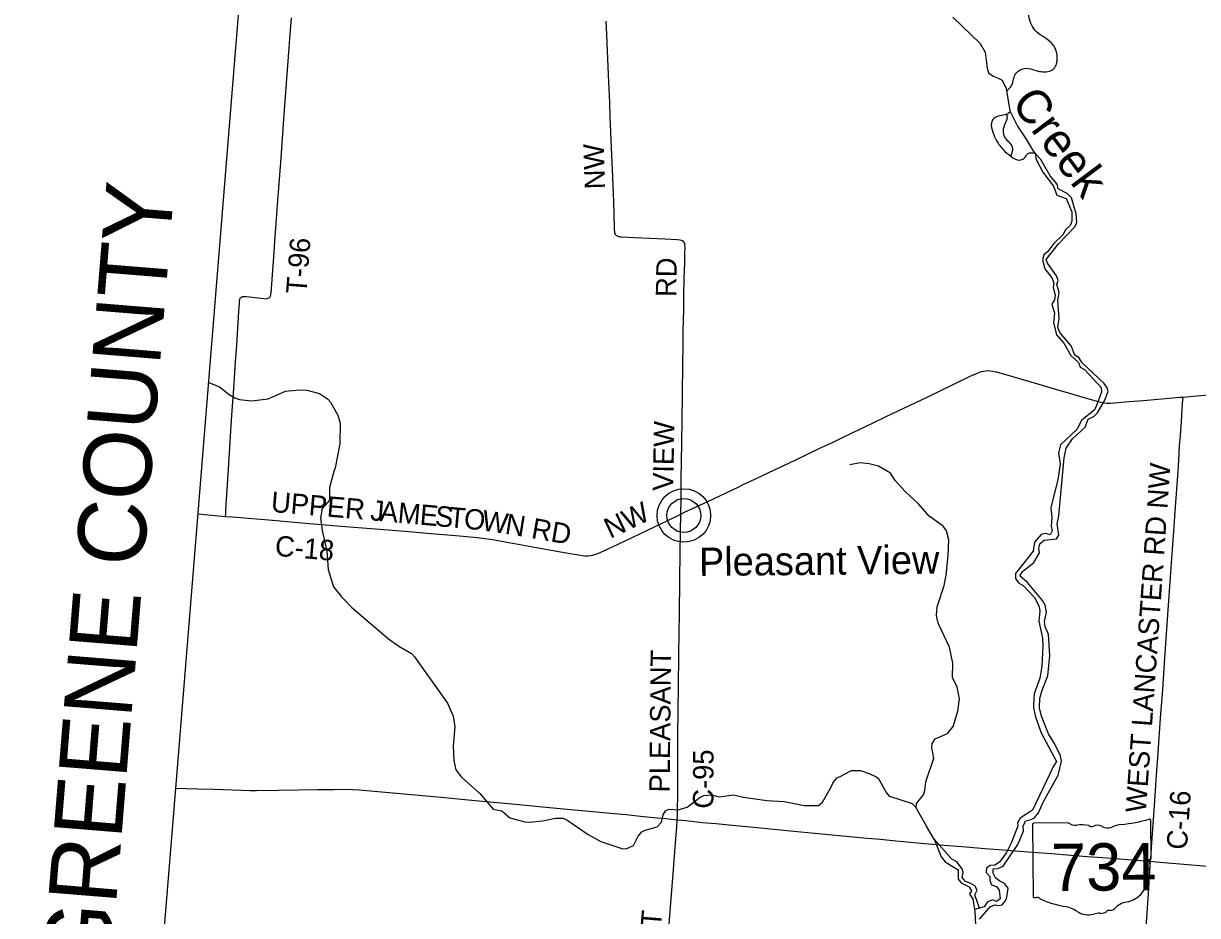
# Model space of a CAD drawing. Extents: x -51392 to 1635000, y 156707 to 696232.
# Drawn here: x 74563 to 91823, y 527835 to 540953 of the extents above; entities that cross this region are included whole.
import ezdxf

# ---------------------------------------------------------------- set-up
doc = ezdxf.new("R2010")
doc.units = 0
for name, color, linetype in [('GM_X_Adjacent_County', 7, 'Continuous'), ('GM_X_Adjacent_County_Text', 7, 'Continuous'), ('GM_X_County', 7, 'Continuous'), ('GM_X_County_Road', 7, 'Continuous'), ('GM_X_County_Road_Text', 7, 'Continuous'), ('GM_X_Major_River', 7, 'Continuous'), ('GM_X_Major_River_Text', 7, 'Continuous'), ('GM_X_Minor_River', 7, 'Continuous'), ('GM_X_State_Route', 7, 'Continuous'), ('GM_X_State_Shield', 7, 'Continuous'), ('GM_X_Township', 7, 'Continuous'), ('GM_X_Township_Road', 7, 'Continuous'), ('GM_X_Township_Road_Text', 7, 'Continuous'), ('GM_X_Unincorporated', 7, 'Continuous'), ('GM_X_Unincorporated_Text', 7, 'Continuous')]:
    doc.layers.add(name, color=color, linetype=linetype)

msp = doc.modelspace()

# ---------------------------------------------------------------- linework, layer by layer
at = {"layer": 'GM_X_Adjacent_County'}
msp.add_lwpolyline([(74563, 502065), (74862, 505867), (75172, 509582), (75227, 510268), (75674, 515788), (75743, 516628), (75955, 519254), (76337, 523966), (76597, 527182), (76801, 529705), (77124, 533695), (77266, 535451), (77972, 544170), (78206, 547064), (78655, 552615), (78677, 552881), (79341, 561012)], dxfattribs=at)
at = {"layer": 'GM_X_County'}
msp.add_lwpolyline([(74563, 502065), (74862, 505867), (75172, 509582), (75227, 510268), (75674, 515788), (75743, 516628), (75955, 519254), (76337, 523966), (76597, 527182), (76801, 529705), (77124, 533695), (77266, 535451), (77972, 544170), (78206, 547064), (78655, 552615), (80912, 552436), (84311, 552167), (86696, 551986), (89363, 551763), (96623, 551154), (109974, 550151)], dxfattribs=at)
at = {"layer": 'GM_X_County_Road'}
for points in [[(84227, 533737), (84231, 533956), (84233, 534251), (84239, 534776), (84250, 535481), (84257, 535957), (84261, 536203), (84263, 536432), (84269, 536744), (84273, 536957), (84278, 537203), (84283, 537433), (84286, 537564), (84288, 537662), (84287, 537695), (84284, 537710), (84280, 537725), (84273, 537739), (84262, 537749), (84249, 537757), (84235, 537762), (84219, 537765), (84171, 537770), (83990, 537779), (83548, 537802), (83351, 537811), (83334, 537812), (83318, 537815), (83301, 537820), (83286, 537828), (83273, 537840), (83264, 537854), (83258, 537870), (83255, 537887), (83253, 537921), (83247, 538167), (83235, 538462), (83208, 539134), (83190, 539576), (83181, 539789), (83162, 540199), (83137, 540789), (83130, 540986)], [(84227, 533737), (84282, 533764), (84624, 533924), (85069, 534136), (85143, 534171), (85314, 534252), (85521, 534351), (85907, 534532), (86292, 534715), (86455, 534793), (86604, 534863), (86841, 534976), (87033, 535068), (87254, 535176), (87506, 535297), (87847, 535459), (88231, 535643), (88482, 535765), (88587, 535812), (88618, 535825), (88650, 535835), (88682, 535842), (88715, 535847), (88748, 535848), (88781, 535846), (88814, 535841), (88863, 535830), (89021, 535786), (89540, 535633), (89682, 535592), (89871, 535536), (90170, 535450), (90360, 535396), (90423, 535380), (90455, 535374), (90487, 535371), (90536, 535370), (90601, 535373), (90814, 535392), (91026, 535410), (91239, 535428), (91353, 535438), (91566, 535456), (91612, 535459)], [(91612, 535459), (91811, 535475), (91991, 535491), (92187, 535509), (92367, 535525), (92612, 535545), (92841, 535564), (93119, 535588), (93282, 535602), (93462, 535617), (93528, 535621), (93561, 535621), (93568, 535620)], [(91131, 528632), (91134, 528674), (91151, 528903), (91184, 529378), (91203, 529672), (91220, 529901), (91243, 530228), (91280, 530735), (91311, 531160), (91342, 531618), (91368, 531978), (91388, 532256), (91407, 532534), (91427, 532812), (91455, 533221), (91473, 533483), (91493, 533777), (91517, 534104), (91536, 534366), (91547, 534530), (91560, 534742), (91570, 534890), (91585, 535102), (91603, 535364), (91607, 535413), (91612, 535459)], [(77132, 533741), (77226, 533732), (77535, 533705)], [(77535, 533705), (77635, 533697), (77929, 533672), (78224, 533647), (78763, 533601), (78943, 533586), (79172, 533566), (79417, 533545), (79859, 533510), (80170, 533485), (80497, 533457), (80971, 533417), (81232, 533392), (81347, 533380), (81428, 533367), (81783, 533304), (82106, 533247), (82543, 533170), (82720, 533138), (82785, 533129), (82818, 533125), (82850, 533124), (82866, 533124), (82898, 533128), (82930, 533134), (82961, 533143), (83007, 533160), (83097, 533200), (83305, 533297), (83838, 533551), (84045, 533651), (84227, 533737)], [(84174, 529243), (84178, 529298), (84180, 529396), (84181, 529609), (84182, 529937), (84184, 530495), (84187, 530839), (84192, 531233), (84203, 532037), (84206, 532234), (84213, 532808), (84218, 533136), (84224, 533496), (84227, 533726), (84227, 533737)], [(83940, 526285), (83951, 526420), (83985, 526845), (84013, 527205), (84031, 527434), (84053, 527712), (84094, 528202), (84114, 528447), (84149, 528905), (84168, 529134), (84174, 529243)], [(91045, 527333), (91085, 527938), (91105, 528233), (91117, 528413), (91131, 528632)]]:
    msp.add_lwpolyline(points, dxfattribs=at)
at = {"layer": 'GM_X_Major_River'}
for points in [[(88223, 541043), (88628, 540656), (88701, 540530), (88728, 540295), (88750, 540225), (88816, 540177), (88894, 540148), (88950, 540120), (89009, 539994), (89064, 539669), (89175, 539442), (89296, 539268), (89412, 539070), (89441, 539038)], [(89441, 539038), (89445, 538960), (89549, 538764), (89706, 538558), (89755, 538428), (89893, 538381), (89976, 538183), (89976, 538044), (89951, 537980), (89883, 537920), (89843, 537843), (89708, 537719), (89624, 537598), (89561, 537548), (89545, 537475), (89577, 537347), (89682, 537212), (89712, 537140), (89700, 537071), (89729, 536955), (89719, 536891), (89681, 536827), (89720, 536693), (89707, 536553), (89749, 536376), (89858, 536251), (89960, 536071), (90075, 535967), (90099, 535901), (90163, 535863), (90404, 535602), (90410, 535532), (90339, 535337), (90308, 535269), (90116, 535116), (90047, 534984), (89810, 534758), (89780, 534640), (89805, 534470), (89770, 534247), (89668, 533832), (89683, 533690), (89673, 533562), (89687, 533494), (89658, 533433), (89586, 533455), (89522, 533437), (89424, 533324), (89405, 533192), (89148, 532866), (89145, 532790), (89191, 532726), (89257, 532687), (89430, 532507), (89496, 532375), (89506, 532309), (89491, 532163), (89542, 531913), (89550, 531795), (89536, 531502), (89502, 531324), (89421, 531097), (89410, 530939), (89412, 530887), (89441, 530755), (89524, 530521), (89751, 530101), (89704, 530029), (89395, 529384), (89213, 529269), (89178, 529197), (89180, 529147), (89077, 528888), (89013, 528764), (88910, 528619), (88844, 528575), (88774, 528573), (88721, 528530), (88715, 528466), (88767, 528408), (88767, 528350), (88796, 528286), (88868, 528264), (88906, 528207), (88920, 528082), (88869, 528042), (88807, 528066), (88733, 528036), (88685, 527965), (88546, 527922)], [(89634, 530505), (89529, 530765), (89498, 530891), (89506, 531029), (89537, 531150), (89624, 531358), (89651, 531659), (89632, 531967), (89612, 532017), (89585, 532079), (89575, 532157), (89604, 532296), (89584, 532398), (89544, 532468), (89321, 532731), (89210, 532831), (89248, 532895), (89300, 532935), (89368, 532985), (89417, 533026), (89499, 533168), (89489, 533234), (89504, 533301), (89570, 533357), (89750, 533374), (89782, 533426), (89761, 533596), (89786, 533712), (89863, 534564), (89892, 534706), (89986, 534845), (90173, 535018), (90214, 535135), (90296, 535175), (90354, 535229), (90457, 535404), (90510, 535541), (90496, 535593), (90452, 535656), (90125, 535963), (90078, 536039), (90020, 536075), (89964, 536211), (89797, 536409), (89769, 536483), (89779, 536551), (89790, 536613), (89771, 536879), (89789, 536996), (89752, 537116), (89772, 537174), (89748, 537244), (89617, 537430), (89597, 537480), (89780, 537711), (90021, 537962), (90050, 538027), (90038, 538155), (89971, 538391), (89907, 538451), (89776, 538522), (89758, 538590), (89658, 538712), (89521, 538950), (89441, 539038)], [(88616, 527783), (88779, 527970), (88847, 527990), (88899, 527980), (88949, 527994), (89000, 528051), (89020, 528103), (89038, 528239), (88983, 528307), (88917, 528339), (88851, 528391), (88819, 528459), (88817, 528521), (88887, 528527), (88966, 528559), (89183, 528881), (89264, 529075), (89258, 529153), (89299, 529228), (89363, 529240), (89427, 529274), (89485, 529347), (89552, 529501), (89776, 529901), (89823, 530105), (89807, 530181), (89720, 530365), (89634, 530505)], [(88546, 527922), (88547, 527893), (88563, 527594)]]:
    msp.add_lwpolyline(points, dxfattribs=at)
at = {"layer": 'GM_X_Minor_River'}
for points in [[(77288, 535675), (77443, 535608), (77586, 535495), (77670, 535447), (77738, 535421), (77916, 535405), (78158, 535435), (78413, 535545), (78621, 535565), (78729, 535561), (78913, 535511), (79033, 535434), (79075, 535384), (79182, 535192), (79216, 535076), (79212, 534771), (79144, 534420), (79127, 534366), (79063, 534130), (79063, 533943), (78955, 533821), (78929, 533685), (78955, 533497), (79023, 533192), (79043, 532923), (79120, 532669), (79242, 532515), (79392, 532366), (79928, 531903), (80081, 531795), (80267, 531690), (80313, 531640), (80798, 530957), (80878, 530766), (80902, 530612), (80882, 530327), (80890, 530113), (80918, 529975), (81000, 529869), (81270, 529628), (81470, 529401), (81594, 529373), (81711, 529271), (81933, 529213), (82003, 529209), (82191, 529225), (82383, 529267), (82496, 529265), (82552, 529243), (82862, 529028), (83052, 528922), (83357, 528819), (83421, 528815), (83533, 528863), (83597, 529002), (83651, 529068), (83701, 529090), (83877, 529140), (83941, 529210), (83965, 529314), (84007, 529380), (84057, 529400), (84188, 529390), (84320, 529430), (84512, 529574), (84564, 529602), (84678, 529610), (84794, 529582), (85003, 529608), (85147, 529574), (85491, 529528), (85747, 529511), (86042, 529453), (86250, 529453), (86310, 529501), (86428, 529707), (86460, 529781), (86514, 529854), (86608, 529897)], [(87684, 529419), (87693, 529481), (87793, 529612), (87816, 529674), (87830, 529802), (87946, 530147), (87916, 530303), (87923, 530367), (87965, 530433), (88147, 530514), (88230, 530613), (88299, 530842), (88324, 531022), (88288, 531192), (88221, 531334), (88226, 531544), (88175, 531780), (88016, 532122), (87998, 532174), (87984, 532252), (87995, 532372), (88096, 532689), (88127, 532838), (88158, 533128), (88167, 533359), (88134, 533491), (88082, 533559), (87876, 533708), (87723, 533891), (87600, 534003), (87526, 534069), (87378, 534230), (87307, 534342), (87135, 534444), (86997, 534479), (86865, 534492), (86711, 534462)], [(87949, 528957), (87839, 529149), (87684, 529419), (87631, 529479), (87301, 529587), (87243, 529651), (87144, 529833), (87092, 529875), (87002, 529918), (86872, 529962), (86732, 529963), (86608, 529897)], [(88615, 527944), (88550, 528137), (88584, 528209), (88550, 528271), (88482, 528309), (88414, 528337), (88363, 528394), (88375, 528467), (88365, 528523), (88284, 528624), (88212, 528664), (87949, 528957)], [(87949, 528957), (88056, 528699), (88115, 528626), (88305, 528506), (88304, 528370), (88346, 528318), (88464, 528257), (88498, 528199), (88468, 528147), (88521, 528079), (88546, 527922)]]:
    msp.add_lwpolyline(points, dxfattribs=at)
for points in [[(89015, 539960), (89086, 540038), (89156, 540223), (89219, 540273), (89293, 540294), (89451, 540260), (89643, 540251), (89711, 540290), (89751, 540360), (89759, 540410), (89714, 540618), (89661, 540680), (89431, 540856), (89332, 541100)], [(89072, 539653), (89018, 539617), (88827, 539556), (88793, 539490), (88813, 539354), (88872, 539224), (88966, 539098), (89077, 539000), (89205, 538943), (89273, 538971), (89330, 539041), (89436, 539044)], [(89018, 539617), (89022, 539565), (88973, 539427), (88970, 539324), (88994, 539270), (89098, 539137), (89077, 539000)]]:
    msp.add_spline(points, degree=3, dxfattribs=at)
at = {"layer": 'GM_X_State_Route'}
for points in [[(76805, 529708), (77121, 529699), (77367, 529691), (77629, 529683), (77891, 529674), (77990, 529673), (78318, 529678), (78892, 529688), (79122, 529690), (79302, 529692), (79401, 529689), (79499, 529683), (79663, 529669), (80153, 529624), (80758, 529569), (81101, 529537), (81313, 529517), (81476, 529501), (81852, 529467), (82195, 529434), (82555, 529399), (82881, 529369), (83192, 529340), (83421, 529319), (83633, 529297), (83878, 529272), (84008, 529260), (84174, 529243), (84302, 529230), (84547, 529205), (84743, 529187), (85037, 529159), (85347, 529128), (85886, 529077), (86197, 529047), (86605, 529007), (86964, 528973), (87160, 528956), (87389, 528934), (87553, 528919), (87700, 528906)], [(87700, 528906), (87814, 528895), (88092, 528870), (88419, 528844), (88697, 528823), (88959, 528801), (89332, 528773)], [(89332, 528773), (89335, 528773), (89678, 528745), (89907, 528727), (90202, 528705), (90431, 528688), (90791, 528659), (91052, 528638), (91131, 528632), (91216, 528625), (91445, 528607), (91968, 528563)]]:
    msp.add_lwpolyline(points, dxfattribs=at)
at = {"layer": 'GM_X_State_Shield'}
for p, q in [((89922, 529196), (89412, 529191)), ((91140, 528681), (91135, 529234)), ((89395, 529173), (89405, 528117)), ((91140, 528681), (91140, 528681))]:
    msp.add_line(p, q, dxfattribs=at)
for centre, major_axis, start_param, end_param in [((89415, 529176), (20.2, 0.2), 1.712693, 3.28349), ((90042, 529320), (196, 2), 4.042523, 4.731795), ((90502, 530642), (1845, 17), 4.814394, 5.042369), ((91116, 529236), (19.4, 0.2), 6.141152, 7.989035), ((90114, 528605), (702, 7), 1.404758, 1.657858), ((90267, 529189), (56.4, 0.5), 3.836095, 5.185415), ((90351, 529068), (117, 1), 0.950623, 2.079405), ((90501, 529237), (141, 1), 4.081561, 5.145723), ((90754, 528881), (371, 3), 1.699011, 2.107814), ((91119, 528679), (20.7, 0.2), 5.05454, 6.418171), ((91212, 528450), (131, 1), 2.387724, 3.262537), ((91136, 528640), (30, 0.3), 1.883978, 3.671073), ((90946, 528569), (180, 2), 5.934695, 6.695948), ((90626, 528375), (462, 4), 5.101752, 6.440018), ((89425, 528114), (20.3, 0.2), 3.00124, 4.508301), ((89427, 528223), (155, 1), 4.665946, 4.897461), ((89461, 528056), (56, 0.5), 0.519207, 1.627899), ((90158, 529012), (1333, 13), 4.195997, 4.488961), ((90826, 527833), (253, 2), 1.647645, 2.488434), ((89774, 527645), (417, 4), 0.823519, 1.323587), ((90221, 528058), (265, 2), 4.026481, 4.996735), ((90377, 527694), (217, 2), 1.495662, 1.94098), ((90394, 527980), (141, 1), 4.691044, 5.507374), ((90522, 527879), (39.7, 0.4), 1.147584, 2.315152), ((90504, 528024), (149, 1), 4.937069, 5.64225)]:
    msp.add_ellipse(centre, major_axis=major_axis, ratio=0.8, start_param=start_param, end_param=end_param, dxfattribs=at)
at = {"layer": 'GM_X_Township'}
msp.add_lwpolyline([(75743, 516628), (75955, 519254), (76337, 523966), (76597, 527182), (76801, 529705), (77124, 533695), (77266, 535451), (77972, 544170)], dxfattribs=at)
at = {"layer": 'GM_X_Township_Road'}
msp.add_lwpolyline([(77535, 533705), (77536, 533734), (77539, 533800), (77556, 534095), (77572, 534324), (77591, 534635), (77618, 535045), (77632, 535258), (77655, 535585), (77671, 535815), (77682, 535978), (77699, 536224), (77730, 536715), (77737, 536847), (77740, 536880), (77744, 536896), (77750, 536911), (77759, 536923), (77771, 536933), (77787, 536938), (77803, 536940), (77836, 536939), (78097, 536906), (78131, 536905), (78147, 536907), (78162, 536912), (78175, 536920), (78187, 536931), (78194, 536945), (78200, 536961), (78204, 536993), (78218, 537190), (78248, 537583), (78260, 537747), (78278, 538009), (78299, 538287), (78321, 538598), (78345, 538909), (78366, 539187), (78380, 539400), (78395, 539613), (78423, 540006), (78448, 540333), (78464, 540529), (78477, 540726), (78501, 541037)], dxfattribs=at)
at = {"layer": 'GM_X_Unincorporated'}
for radius in [393, 249]:
    msp.add_circle((84271, 533718), radius, dxfattribs=at)

# ---------------------------------------------------------------- texts
at = {"layer": 'GM_X_Adjacent_County_Text'}
msp.add_text('GREENE COUNTY', height=1000, rotation=85.3552, dxfattribs=at).set_placement((75838, 526946))
at = {"layer": 'GM_X_County_Road_Text'}
for s, rotation, p in [('NW', 91.7751, (83113, 538519)), ('RD', 89.044, (84158, 536929)), ('VIEW', 88.9618, (84114, 534077)), ('WEST LANCASTER RD NW', 85.9625, (91063, 529340)), ('UPPER', 355.2234, (78193, 533771)), ('J', 354.9289, (79653, 533648)), ('A', 354.9269, (79793, 533636)), ('M', 354.9266, (80056, 533612)), ('E', 354.9268, (80380, 533584)), ('S', 354.9277, (80604, 533564)), ('NW', 25.2905, (83189, 533373)), ('T', 354.9239, (80805, 533546)), ('O', 354.5461, (81028, 533526)), ('W', 351.5431, (81287, 533502)), ('N', 350.8759, (81630, 533451)), ('RD', 350.1011, (82016, 533387)), ('C-18', 355.0335, (78251, 533126)), ('PLEASANT', 89.4652, (84063, 529644)), ('C-95', 89.8537, (84705, 529406)), ('C-16', 86.0766, (91666, 528796)), ('PLEASANT', 85.4402, (83787, 525809))]:
    msp.add_text(s, height=300, rotation=rotation, dxfattribs=at).set_placement(p)
at = {"layer": 'GM_X_Major_River_Text'}
msp.add_text('Creek', height=500.1, rotation=306.7365, dxfattribs=at).set_placement((89072, 539781))
at = {"layer": 'GM_X_State_Shield'}
msp.add_text('734', height=696.1, rotation=0.5385, dxfattribs=at).set_placement((89670, 528194))
at = {"layer": 'GM_X_Township_Road_Text'}
msp.add_text('T-96', height=300, rotation=85.5967, dxfattribs=at).set_placement((78721, 536969))
at = {"layer": 'GM_X_Unincorporated_Text'}
msp.add_text('Pleasant View', height=417, rotation=0.5386, dxfattribs=at).set_placement((84495, 532828))

doc.saveas('drawing.dxf')
